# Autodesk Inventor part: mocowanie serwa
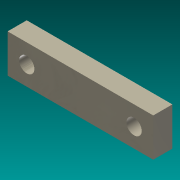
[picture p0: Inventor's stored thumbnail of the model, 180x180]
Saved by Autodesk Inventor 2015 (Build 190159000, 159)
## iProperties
Created: 2016-02
Part Number: mocowanie serwa
Material: Generic
Document SubType Name: Modeling
Designer: Rafał
Density: 1 g/cm^3
Appearance: Light Beige
Author: Rafał
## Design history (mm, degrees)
sketch "Sketch1"
  geometry: L1 (0, 0)-(38, 0); L2 (38, 0)-(38, 10); L3 (38, 10)-(0, 10); L4 (0, 10)-(0, 0); L5 (19, 10)-(19, 0); C1 r 2 at (33, 5); C2 r 2 at (5, 5)
  constraints: 10 end point, 2 centre point, 2 midpoint, 2 parallel, 1 horizontal, 1 perpendicular, 1 symmetric about line, 1 other
  dimensions: "d0" = 38 distance of L3.end L2.end; "d1" = 10 distance of L2.end L1.end; "d2" = 4 diameter of C1; "d3" = 5 distance from line of L2 C1.centre; "d4" = 5 distance from line of C1.centre L1
extrude "Extrusion1" new body sketch "Sketch1" distance "d5" = 5; taper "d6" = 0 deg
body "Solid1"
